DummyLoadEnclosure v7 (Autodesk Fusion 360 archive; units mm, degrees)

design "DummyLoadEnclosure" references "2.8 TFT Module"
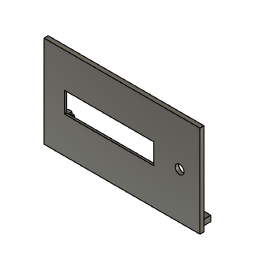
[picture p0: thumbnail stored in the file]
sketch "Sketch1" plane through (0, 0, 0) normal (0, 0, 1) x axis (1, 0, 0)
  line L1 (-60, -50) -> (60, -50)
  line L2 (-60, 50) -> (-60, -50)
  line L3 (60, 50) -> (-60, 50)
  line L4 (60, -50) -> (60, 50)
  line L5 (-60, 50) -> (60, -50)
  line L6 (60, 50) -> (-60, -50)
  point P6 (0, 0)
  point P1 (0, 0)
  point P4 (-60, 50)
  point P5 (60, 50)
  point P3 (-60, -50)
  horizontal L1
  perpendicular L1 L2
  parallel L1 L3
  parallel L2 L4
  coincident L5 P6
  coincident L6 P6
  coincident P1 P6
  dimension "d1" distance P4 P5 = 120
  dimension "d2" distance P3 P4 = 100
extrude "Extrude1" new body sketch "Sketch1" profile of L1 L2 L3 L4 along normal blind 70
shell "Shell1" innerThickness 3
split "Split1"
split "Split2"
split "Split3"
split "Split4"
combine "Combine1"
sketch "Sketch2" plane through (0, -47, 0) normal (0, -1, 0) x axis (1, 0, 0)
  line L1 (57, 70) -> (57, 67)
  line L2 (-57, 70) -> (57, 70)
  line L3 (-57, 67) -> (-57, 70)
  line L4 (57, 67) -> (-57, 67)
  line L5 (57, 70) -> (-57, 70)
  line L6 (57, 67) -> (57, 70)
  line L7 (-57, 67) -> (57, 67)
  line L8 (-57, 70) -> (-57, 67)
  point P2 (57, 67)
  point P8 (57, 67)
  point P4 (-57, 70)
  point P6 (-57, 70)
  horizontal L5
  vertical L6
  horizontal L7
  vertical L8
  coincident P2 P8
  coincident P4 P6
extrude "Extrude2" add sketch "Sketch2" along normal blind 10
sketch "Sketch3" plane through (0, -50, 0) normal (0, -1, 0) x axis (1, 0, 0)
  line L1 (57, 0) -> (57, 67)
  line L2 (60, 0) -> (57, 0)
  line L3 (60, 70) -> (60, 0)
  line L4 (57, 70) -> (60, 70)
  line L5 (57, 67) -> (57, 70)
  line L6 (60, 70) -> (57, 70)
  line L7 (60, 0) -> (60, 70)
  line L8 (57, 0) -> (60, 0)
  line L9 (57, 70) -> (57, 0)
  line L10 (-57, 70) -> (-60, 70)
  line L11 (-57, 0) -> (-57, 70)
  line L12 (-60, 0) -> (-57, 0)
  line L13 (-60, 70) -> (-60, 0)
  point P4 (60, 0)
  point P9 (60, 0)
  point P6 (57, 70)
  point P7 (57, 70)
  horizontal L6
  vertical L7
  horizontal L8
  vertical L9
  coincident P4 P9
  coincident P6 P7
  horizontal L10
  vertical L11
  horizontal L12
  vertical L13
extrude "Extrude3" add sketch "Sketch3" profile of L1 L2 L3 L4 L5 L6 L7 L8 L9 along normal blind 7
extrude "Extrude4" add sketch "Sketch3" profile of L10 L11 L12 L13 along normal blind 7
work_plane "WorkPlane1" AlongDistance -3
draft "Draft1" Angle1 -6 Angle2 0
combine "Combine2"
work_plane "WorkPlane5" AlongDistance -8.5 (= "( -17 / 2 ) * 1 mm")
work_plane "WorkPlane6" AlongDistance -8.5 (= "( -17 / 2 ) * 1 mm")
work_plane "WorkPlane7" AlongDistance -5
component_insert "Component Insert"
work_plane "WorkPlane8" AlongDistance -33
work_plane "WorkPlane9" AlongDistance -8
work_plane "WorkPlane10" AlongDistance -8
work_plane "WorkPlane11" AlongDistance -10.5
sketch "Sketch7" plane through (0, -47, 0) normal (0, 1, 0) x axis (-1, 0, 0)
  line L1 (-57, 67) -> (57, 67)
  line L2 (-57, 0) -> (-57, 67)
  line L3 (57, 0) -> (-57, 0)
  line L4 (57, 67) -> (57, 0)
  line L5 (46.5, 59) -> (-24, 59)
  line L6 (46.5, 8) -> (46.5, 59)
  line L7 (-24, 8) -> (46.5, 8)
  line L8 (-24, 59) -> (-24, 8)
  horizontal L5
  vertical L6
  horizontal L7
  vertical L8
position "Position4"
sketch "Sketch10" plane through (0, -47, 0) normal (0, 1, 0) x axis (-1, 0, 0)
  line L1 (-57, 67) -> (57, 67)
  line L2 (-57, 0) -> (-57, 67)
  line L3 (57, 0) -> (-57, 0)
  line L4 (57, 67) -> (57, 0)
  circle C1 centre (-27.3414, 55.3636) radius 1.6129
  circle C2 centre (48.757, 55.3636) radius 1.6129
  circle C3 centre (48.757, 11.447) radius 1.6129
  circle C4 centre (-27.3414, 11.447) radius 1.6129
  circle C5 centre (-27.3414, 55.3636) radius 3
  circle C6 centre (48.757, 55.3636) radius 3
  circle C7 centre (48.757, 11.447) radius 3
  circle C8 centre (-27.3414, 11.447) radius 3
  concentric C1 C5
  concentric C2 C6
  concentric C3 C7
  concentric C4 C8
  dimension "d34" diameter C5 = 6
  dimension "d35" diameter C6 = 6
  dimension "d36" diameter C7 = 6
  dimension "d37" diameter C8 = 6
sketch "Sketch11" plane through (0, -47, 0) normal (0, 1, 0) x axis (-1, 0, 0)
sketch "Sketch12" plane through (57, 0, 0) normal (-1, 0, 0) x axis (0, -1, 0)
  line L1 (-47, 67) -> (57, 67)
  line L2 (-47, 70) -> (-47, 67)
  line L3 (-50, 70) -> (-47, 70)
  line L4 (-50, 0) -> (-50, 70)
  line L5 (49.958, 0) -> (-50, 0)
  line L6 (57, 67) -> (49.958, 0)
  line L7 (45.9991, 67) -> (46.9991, 67)
  line L8 (45.9991, 3) -> (45.9991, 67)
  line L9 (46.9991, 3) -> (45.9991, 3)
  line L10 (46.9991, 67) -> (46.9991, 3)
  point P8 (46.9991, 67)
  point P9 (45.9991, 67)
  horizontal L7
  vertical L8
  horizontal L9
  vertical L10
  coincident L1 P8
  dimension "d58" distance P8 P9 = 1
extrude "Extrude14" add sketch "Sketch12" profile of L1 L7 L8 L9 L10 along normal blind 1
sketch "Sketch13" plane through (0, 0, 67) normal (0, 0, -1) x axis (1, 0, 0)
  line L1 (56, 45.9991) -> (57, 45.9991)
  line L2 (56, 46.9991) -> (56, 45.9991)
  line L3 (57, 46.9991) -> (56, 46.9991)
  line L4 (57, 57) -> (57, 46.9991)
  line L5 (-57, 57) -> (57, 57)
  line L6 (-57, -47) -> (-57, 57)
  line L7 (57, -47) -> (-57, -47)
  line L8 (57, 45.9991) -> (57, -47)
  line L9 (-57, 46.9991) -> (57, 46.9991)
  line L10 (-57, 45.9991) -> (-57, 46.9991)
  line L11 (57, 45.9991) -> (-57, 45.9991)
  line L12 (57, 46.9991) -> (57, 45.9991)
  point P5 (57, 46.9991)
  point P10 (57, 46.9991)
  point P11 (-57, 46.9991)
  point P13 (57, 45.9991)
  horizontal L9
  vertical L10
  horizontal L11
  vertical L12
  coincident P5 P10
  dimension "d61" distance P10 P11 = 114
  dimension "d62" distance P10 P13 = 1
extrude "Extrude15" add sketch "Sketch13" profile of L2 L6 L9 L10 L11 along normal blind 1
work_plane "WorkPlane12"
mirror "Mirror1" mirrorStitchTolerance 0.1
extrude "Extrude16" add of existing geometry blind 3
combine "Combine8"
sketch "Sketch14" plane through (0, 0, 67) normal (0, 0, -1) x axis (1, 0, 0)
  line L1 (57, 46.9991) -> (-57, 46.9991)
  line L2 (57, 57) -> (57, 46.9991)
  line L3 (-57, 57) -> (57, 57)
  line L4 (-57, 46.9991) -> (-57, 57)
work_plane "WorkPlane13" AlongDistance 3
sketch "Sketch15" plane through (0, 0, 67) normal (0, 0, -1) x axis (1, 0, 0)
  line L1 (-57, 50) -> (57, 50)
  line L2 (-57, 51) -> (-57, 50)
  line L3 (57, 51) -> (-57, 51)
  line L4 (57, 50) -> (57, 51)
  point P2 (57, 50)
  point P3 (-57, 50)
  point P5 (57, 51)
  horizontal L1
  vertical L2
  horizontal L3
  vertical L4
  dimension "d70" distance P2 P3 = 114
  dimension "d71" distance P2 P5 = 1
extrude "Extrude17" add sketch "Sketch15" along normal blind 1
offset_faces "OffsetFaces1" distance -0.2
position "Position5"
work_plane "WorkPlane16" AlongDistance -15
work_plane "WorkPlane15"
hole "Hole5" HoleDepth 5 HoleDiameter 6.5 TipAngle 180
chamfer "Chamfer2" distance 0.5
work_plane "WorkPlane17" AlongDistance -3
sketch "Sketch16" plane through (0, -47, 0) normal (0, 1, 0) x axis (-1, 0, 0)
  line L1 (-57, 67) -> (57, 67)
  line L2 (-57, 0) -> (-57, 67)
  line L3 (57, 0) -> (-57, 0)
  line L4 (57, 67) -> (57, 0)
  line L5 (-57, 3) -> (56.9, 3)
  line L6 (-57, 7) -> (-57, 3)
  line L7 (56.9, 7) -> (-57, 7)
  line L8 (56.9, 3) -> (56.9, 7)
  circle C1 centre (-41.9997, 33.4999) radius 3.75
  point P7 (56.9, 3)
  point P10 (56.9, 7)
  horizontal L5
  vertical L6
  horizontal L7
  vertical L8
  dimension "d96" distance P7 P10 = 4
extrude "Extrude19" add sketch "Sketch16" profile of L2 L5 L6 L7 L8 along normal blind 6
combine "Combine9"
extrude "Extrude20" cut of existing geometry blind -1
extrude "Extrude21" cut of existing geometry blind -0.9
work_plane "WorkPlane18"
sketch "Sketch17" plane through (0, 0, 7) normal (0, 0, 1) x axis (-1, 0, 0)
  line L1 (56, 46.9991) -> (56, 41)
  line L2 (56.9, 46.9991) -> (56, 46.9991)
  line L3 (56.9, 47) -> (56.9, 46.9991)
  line L4 (-57, 47) -> (56.9, 47)
  line L5 (-57, 46.9991) -> (-57, 47)
  line L6 (-56, 46.9991) -> (-57, 46.9991)
  line L7 (-56, 41) -> (-56, 46.9991)
  line L8 (56, 41) -> (-56, 41)
  dimension "d105" R-Pattern1-uDistance = 100
  dimension "d106" R-Pattern1-vDistance = 0
hole "Hole6" HoleDepth 50 HoleDiameter 1.6 TipAngle 180
sketch "Sketch18" plane through (0, 0, 0) normal (0, 0, -1) x axis (1, 0, 0)
  line L1 (57, -47) -> (-57, -47)
  line L2 (57, 47) -> (57, -47)
  line L3 (-57, 47) -> (57, 47)
  line L4 (-57, -47) -> (-57, 47)
  circle C1 centre (-25.0001, 44) radius 0.8
  circle C2 centre (24.9999, 44) radius 0.8
  circle C3 centre (49.9999, 44) radius 0.8
  circle C4 centre (-0.0001, 44) radius 0.8
  circle C5 centre (-50.0001, 44) radius 0.8
  circle C6 centre (49.9999, 44) radius 1.1
  circle C7 centre (24.9999, 44) radius 1.1
  circle C8 centre (-0.0001, 44) radius 1.1
  circle C9 centre (-25.0001, 44) radius 1.1
  circle C10 centre (-50.0001, 44) radius 1.1
  concentric C3 C6
  concentric C2 C7
  concentric C4 C8
  concentric C1 C9
  concentric C5 C10
  dimension "d110" diameter C6 = 2.2
  dimension "d111" diameter C7 = 2.2
  dimension "d112" diameter C8 = 2.2
  dimension "d113" diameter C9 = 2.2
  dimension "d114" diameter C10 = 2.2
hole "Hole7" HoleDepth 3 HoleDiameter 2.2 TipAngle 180
sketch "Sketch19" plane through (0, 0, 0) normal (0, 0, -1) x axis (1, 0, 0)
  line L1 (57, -47) -> (-57, -47)
  line L2 (57, 47) -> (57, -47)
  line L3 (-57, 47) -> (57, 47)
  line L4 (-57, -47) -> (-57, 47)
  line L5 (-52, 47) -> (-57, 47)
  line L6 (-52, 42) -> (-52, 47)
  line L7 (-57, 42) -> (-52, 42)
  line L8 (-57, 47) -> (-57, 42)
  line L9 (52, 47) -> (57, 47)
  line L10 (52, 42) -> (52, 47)
  line L11 (57, 42) -> (52, 42)
  line L12 (57, 47) -> (57, 42)
  line L13 (-52, -47) -> (-57, -47)
  line L14 (-52, -42) -> (-52, -47)
  line L15 (-57, -42) -> (-52, -42)
  line L16 (-57, -47) -> (-57, -42)
  line L17 (52, -47) -> (57, -47)
  line L18 (52, -42) -> (52, -47)
  line L19 (57, -42) -> (52, -42)
  line L20 (57, -47) -> (57, -42)
  circle C1 centre (24.9999, 44) radius 1.1
  circle C2 centre (-25.0001, 44) radius 1.1
  circle C3 centre (-50.0001, 44) radius 1.1
  circle C4 centre (-0.0001, 44) radius 1.1
  circle C5 centre (49.9999, 44) radius 1.1
  point P10 (-57, 47)
  point P11 (-57, 47)
  point P9 (57, 47)
  point P15 (57, 47)
  point P7 (-57, -47)
  point P19 (-57, -47)
  point P8 (57, -47)
  point P23 (57, -47)
  point P12 (-52, 47)
  point P14 (-57, 42)
  point P16 (52, 47)
  point P18 (57, 42)
  point P20 (-52, -47)
  point P22 (-57, -42)
  point P24 (52, -47)
  point P26 (57, -42)
  horizontal L5
  vertical L6
  horizontal L7
  vertical L8
  coincident P10 P11
  horizontal L9
  vertical L10
  horizontal L11
  vertical L12
  coincident P9 P15
  horizontal L13
  vertical L14
  horizontal L15
  vertical L16
  coincident P7 P19
  horizontal L17
  vertical L18
  horizontal L19
  vertical L20
  coincident P8 P23
  dimension "d118" distance P11 P12 = 5
  dimension "d119" distance P11 P14 = 5
  dimension "d120" distance P15 P16 = 5
  dimension "d121" distance P15 P18 = 5
  dimension "d122" distance P19 P20 = 5
  dimension "d123" distance P19 P22 = 5
  dimension "d124" distance P23 P24 = 5
  dimension "d125" distance P23 P26 = 5
extrude "Extrude22" add sketch "Sketch19" profile of L1 L2 L3 L4 L5 L6 L7 L8 L9 L10 L11 L12 L13 L14 L15 L16 L17 L18 L19 L20 along normal blind 2
chamfer "Chamfer7" distance 0.5
chamfer "Chamfer8" distance 0.5
chamfer "Chamfer9" distance 0.5
chamfer "Chamfer10" distance 0.5
chamfer "Chamfer11" distance 0.5
work_plane "WorkPlane19"
sketch "Sketch20" plane through (0, 47, 0) normal (0, -1, 0) x axis (1, 0, 0)
  line L1 (-57, 67) -> (57, 67)
  line L2 (-57, 0) -> (-57, 67)
  line L3 (57, 0) -> (-57, 0)
  line L4 (57, 67) -> (57, 0)
  line L5 (56, 2.9999) -> (-56, 2.9999)
  line L6 (56, 6.9999) -> (56, 2.9999)
  line L7 (-56, 6.9999) -> (56, 6.9999)
  line L8 (-56, 2.9999) -> (-56, 6.9999)
  line L9 (57, 3) -> (-57, 3)
  point P6 (-56, 2.9999)
  point P9 (-56, 6.9999)
  horizontal L5
  vertical L6
  horizontal L7
  vertical L8
  dimension "d133" distance P6 P9 = 4
  dimension "d134" distance L2 L8 = 1
  dimension "d136" distance L4 L6 = 1
extrude "Extrude23" add sketch "Sketch20" profile of L6 L7 L8 L9 along normal blind 6
sketch "Sketch21" plane through (0, 0, 6.9999) normal (0, 0, 1) x axis (-1, 0, 0)
  line L1 (56, -47) -> (-56, -47)
  line L2 (56, -41) -> (56, -47)
  line L3 (-56, -41) -> (56, -41)
  line L4 (-56, -47) -> (-56, -41)
  point P6 (50, -44)
  dimension "d139" distance L1 P6 = 3
  dimension "d140" distance L2 P6 = 6
  dimension "d143" R-Pattern1-uDistance = -100
  dimension "d144" R-Pattern1-vDistance = 0
hole "Hole8" HoleDepth 10 HoleDiameter 1.6 TipAngle 180
sketch "Sketch22" plane through (0, 0, 0) normal (0, 0, -1) x axis (1, 0, 0)
  line L1 (-52, -47) -> (-52, -42)
  line L2 (52, -47) -> (-52, -47)
  line L3 (52, -42) -> (52, -47)
  line L4 (57, -42) -> (52, -42)
  line L5 (57, 42) -> (57, -42)
  line L6 (52, 42) -> (57, 42)
  line L7 (52, 47) -> (52, 42)
  line L8 (-52, 47) -> (52, 47)
  line L9 (-52, 42) -> (-52, 47)
  line L10 (-57, 42) -> (-52, 42)
  line L11 (-57, -42) -> (-57, 42)
  line L12 (-52, -42) -> (-57, -42)
  circle C1 centre (50, -44) radius 0.8
  circle C2 centre (-25, -44) radius 0.8
  circle C3 centre (-50, -44) radius 0.8
  circle C4 centre (0, -44) radius 0.8
  circle C5 centre (25, -44) radius 0.8
  circle C6 centre (24.9999, 44) radius 1.6
  circle C7 centre (-25.0001, 44) radius 1.6
  circle C8 centre (-50.0001, 44) radius 1.6
  circle C9 centre (-0.0001, 44) radius 1.6
  circle C10 centre (49.9999, 44) radius 1.6
  circle C11 centre (-50, -44) radius 1.1
  circle C12 centre (-25, -44) radius 1.1
  circle C13 centre (0, -44) radius 1.1
  circle C14 centre (25, -44) radius 1.1
  circle C15 centre (50, -44) radius 1.1
  concentric C3 C11
  concentric C2 C12
  concentric C4 C13
  concentric C5 C14
  concentric C1 C15
  dimension "d148" diameter C11 = 2.2
  dimension "d149" diameter C12 = 2.2
  dimension "d150" diameter C13 = 2.2
  dimension "d151" diameter C14 = 2.2
  dimension "d152" diameter C15 = 2.2
hole "Hole9" HoleDepth 4 HoleDiameter 2.2 TipAngle 180
chamfer "Chamfer12" distance 0.5
chamfer "Chamfer13" distance 0.5
chamfer "Chamfer14" distance 0.5
hole "Hole10" HoleDepth 4 HoleDiameter 8 TipAngle 180 RefDim1 10 RefDim2 25
hole "Hole11" HoleDepth 4 HoleDiameter 6.5 TipAngle 180 RefDim1 70 RefDim2 25
extrude "Extrude24" add of existing geometry blind 1
sketch "Sketch23" plane through (0, 0, 67) normal (0, 0, -1) x axis (1, 0, 0)
  line L1 (-57, 45.9991) -> (57, 45.9991)
  line L2 (-57, -51) -> (-57, 45.9991)
  line L3 (57, -51) -> (-57, -51)
  line L4 (57, 45.9991) -> (57, -51)
  line L5 (-57, -51) -> (57, -51)
  line L6 (-57, -50) -> (-57, -51)
  line L7 (57, -50) -> (-57, -50)
  line L8 (57, -51) -> (57, -50)
  line L9 (-57, -47) -> (57, -47)
  line L10 (-57, -46) -> (-57, -47)
  line L11 (57, -46) -> (-57, -46)
  line L12 (57, -47) -> (57, -46)
  point P5 (57, -51)
  point P6 (57, -51)
  point P10 (57, -47)
  point P9 (57, -50)
  point P11 (-57, -47)
  point P13 (57, -46)
  horizontal L5
  vertical L6
  horizontal L7
  vertical L8
  coincident P5 P6
  horizontal L9
  vertical L10
  horizontal L11
  vertical L12
  coincident L4 P10
  dimension "d171" distance P6 P9 = 1
  dimension "d172" distance P10 P11 = 114
  dimension "d173" distance P10 P13 = 1
  dimension "d174" distance L7 L9 = 3
extrude "Extrude25" add sketch "Sketch23" profile of L2 L3 L4 L5 L6 L7 L8 L9 L10 L11 L12 along normal blind 2
offset_faces "OffsetFaces2" distance -0.2
offset_faces "OffsetFaces3" distance -0.2
offset_faces "OffsetFaces4" distance -0.2
offset_faces "OffsetFaces5" distance -0.2
offset_faces "OffsetFaces6" distance -0.2
chamfer "Chamfer15" distance 0.5
chamfer "Chamfer16" distance 0.5
extrude "Extrude26" cut of existing geometry blind -0.2
extrude "Extrude27" add of existing geometry blind 1
offset_faces "OffsetFaces7" distance -0.2
offset_faces "OffsetFaces8" distance -0.2
offset_faces "OffsetFaces9" distance -0.2
offset_faces "OffsetFaces10" distance -0.1
sketch "Sketch24" plane through (0, 0, 3) normal (0, 0, 1) x axis (-1, 0, 0)
  line L1 (57, -47) -> (-57, -47)
  line L2 (57, 47) -> (57, -47)
  line L3 (-57, 47) -> (57, 47)
  line L4 (-57, -47) -> (-57, 47)
  line L5 (51, 9) -> (57, 9)
  line L6 (51, -9) -> (51, 9)
  line L7 (57, -9) -> (51, -9)
  line L8 (57, 9) -> (57, -9)
  line L9 (68.4, 0) -> (-68.4, 0)
  circle C1 centre (25, -44) radius 1.1
  circle C2 centre (-25, -44) radius 1.1
  circle C3 centre (-50, -44) radius 1.1
  circle C4 centre (0, -44) radius 1.1
  circle C5 centre (50, -44) radius 1.1
  circle C6 centre (-24.9999, 44) radius 1.1
  circle C7 centre (25.0001, 44) radius 1.1
  circle C8 centre (50.0001, 44) radius 1.1
  circle C9 centre (0.0001, 44) radius 1.1
  circle C10 centre (-49.9999, 44) radius 1.1
  point P16 (57, 9)
  horizontal L5
  vertical L6
  horizontal L7
  vertical L8
  coincident L2 P16
  dimension "d192" distance L7 L9 = 9
  dimension "d193" distance L5 L9 = 9
  dimension "d194" distance L2 L6 = 6
extrude "Extrude28" add sketch "Sketch24" profile of L2 L5 L6 L7 L8 L9 along normal blind 6
work_plane "WorkPlane20"
mirror "Mirror2" mirrorStitchTolerance 0.1
hole "Hole12" HoleDepth 6 HoleDiameter 2.5 TipAngle 180 RefDim1 3 RefDim2 9
mirror "Mirror3" mirrorStitchTolerance 0.1
thread "Thread5" ThreadOffset 0 ThreadLength 10
thread "Thread6" ThreadOffset 0 ThreadLength 10
chamfer "Chamfer17" distance 0.5
chamfer "Chamfer18" distance 0.5
sketch "Sketch25" plane through (57, 0, 0) normal (-1, 0, 0) x axis (0, -1, 0)
  line L1 (-46, 65) -> (-46, 67)
  line L2 (-46.8, 65) -> (-46, 65)
  line L3 (-46.8, 67.2) -> (-46.8, 65)
  line L4 (-50, 67.2) -> (-46.8, 67.2)
  line L5 (-50, 65) -> (-50, 67.2)
  line L6 (-51, 65) -> (-50, 65)
  line L7 (-51, 0) -> (-51, 65)
  line L8 (49.958, 0) -> (-51, 0)
  line L9 (57, 67) -> (49.958, 0)
  line L10 (51, 67) -> (57, 67)
  line L11 (51, 66) -> (51, 67)
  line L12 (50.2, 66) -> (51, 66)
  line L13 (50.2, 67) -> (50.2, 66)
  line L14 (46.9991, 67) -> (50.2, 67)
  line L15 (46.9991, 3) -> (46.9991, 67)
  line L16 (45.9991, 3) -> (46.9991, 3)
  line L17 (45.9991, 67) -> (45.9991, 3)
  line L18 (-46, 67) -> (45.9991, 67)
  circle C1 centre (0, 6) radius 1.75
  dimension "d208" diameter C1 = 3.5
extrude "Extrude29" cut sketch "Sketch25" profile of C1 against normal blind 3
sketch "Sketch26" plane through (-57, 0, 0) normal (1, 0, 0) x axis (0, 1, 0)
  line L1 (46, 67) -> (46, 65)
  line L2 (-45.9991, 67) -> (46, 67)
  line L3 (-45.9991, 3) -> (-45.9991, 67)
  line L4 (-46.9991, 3) -> (-45.9991, 3)
  line L5 (-46.9991, 67) -> (-46.9991, 3)
  line L6 (-50.2, 67) -> (-46.9991, 67)
  line L7 (-50.2, 66) -> (-50.2, 67)
  line L8 (-51, 66) -> (-50.2, 66)
  line L9 (-51, 67) -> (-51, 66)
  line L10 (-57, 67) -> (-51, 67)
  line L11 (-49.958, 0) -> (-57, 67)
  line L12 (51, 0) -> (-49.958, 0)
  line L13 (51, 65) -> (51, 0)
  line L14 (50, 65) -> (51, 65)
  line L15 (50, 67.2) -> (50, 65)
  line L16 (46.8, 67.2) -> (50, 67.2)
  line L17 (46.8, 65) -> (46.8, 67.2)
  line L18 (46, 65) -> (46.8, 65)
  circle C1 centre (0, 6) radius 1.75
  dimension "d211" diameter C1 = 3.5
extrude "Extrude30" cut sketch "Sketch26" profile of C1 against normal blind 3
chamfer "Chamfer19" distance 0.5
chamfer "Chamfer20" distance 0.5
chamfer "Chamfer21" distance 0.5
sketch "Sketch27" plane through (0, 0, 9) normal (0, 0, 1) x axis (-1, 0, 0)
  line L1 (57, 9) -> (57, -9)
  line L2 (51, 9) -> (57, 9)
  line L3 (51, -9) -> (51, 9)
  line L4 (57, -9) -> (51, -9)
  circle C1 centre (54, 6) radius 0.8
  circle C2 centre (54, -6) radius 0.8
  point P6 (54, 6)
  point P8 (54, 6)
  point P7 (54, -6)
  point P9 (54, -6)
  coincident P6 P8
  coincident P7 P9
  dimension "d217" distance L3 P6 = 3
  dimension "d218" distance L2 P6 = 3
  dimension "d219" distance L4 P7 = 3
  dimension "d220" distance L3 P7 = 3
  dimension "d221" diameter C1 = 1.6
  dimension "d222" diameter C2 = 1.6
extrude "Extrude31" cut sketch "Sketch27" profile of C1 against normal blind 10
extrude "Extrude32" cut sketch "Sketch27" profile of C2 against normal blind 10
sketch "Sketch28" plane through (0, 0, 0) normal (0, 0, -1) x axis (1, 0, 0)
  line L1 (57, 42) -> (57, -42)
  line L2 (52, 42) -> (57, 42)
  line L3 (52, 47) -> (52, 42)
  line L4 (-52, 47) -> (52, 47)
  line L5 (-52, 42) -> (-52, 47)
  line L6 (-57, 42) -> (-52, 42)
  line L7 (-57, -42) -> (-57, 42)
  line L8 (-52, -42) -> (-57, -42)
  line L9 (-52, -47) -> (-52, -42)
  line L10 (52, -47) -> (-52, -47)
  line L11 (52, -42) -> (52, -47)
  line L12 (57, -42) -> (52, -42)
  circle C1 centre (-54, -6) radius 0.8
  circle C2 centre (-54, 6) radius 0.8
  circle C3 centre (25, -44) radius 1.6
  circle C4 centre (-25, -44) radius 1.6
  circle C5 centre (49.9999, 44) radius 1.6
  circle C6 centre (-0.0001, 44) radius 1.6
  circle C7 centre (-50.0001, 44) radius 1.6
  circle C8 centre (-25.0001, 44) radius 1.6
  circle C9 centre (24.9999, 44) radius 1.6
  circle C10 centre (-50, -44) radius 1.6
  circle C11 centre (0, -44) radius 1.6
  circle C12 centre (50, -44) radius 1.6
  circle C13 centre (-54, 6) radius 1.1
  circle C14 centre (-54, -6) radius 1.1
  concentric C2 C13
  concentric C1 C14
  dimension "d227" diameter C13 = 2.2
  dimension "d228" diameter C14 = 2.2
extrude "Extrude33" cut sketch "Sketch28" profile of C1 C2 C13 C14 against normal blind 3
split "Split5" bodies "Base (1)", "DummyLoadBaseTopMount"
remove_body "RemoveBody1"
mirror "Mirror4" mirrorStitchTolerance 0.1 bodies "DummyLoadBase"
extrude "Extrude34" cut of existing geometry blind -10
extrude "Extrude35" cut of existing geometry blind -10
remove_body "RemoveBody2"
remove_body "RemoveBody3"
sketch "Sketch29" plane through (0, 47, 0) normal (0, -1, 0) x axis (1, 0, 0)
  line L1 (55.8, 6.9999) -> (-55.8, 6.9999)
  line L2 (55.8, 3) -> (55.8, 6.9999)
  line L3 (-55.8, 3) -> (55.8, 3)
  line L4 (-55.8, 6.9999) -> (-55.8, 3)
  line L5 (-56.8, 67) -> (56.8, 67)
  line L6 (-56.8, 0) -> (-56.8, 67)
  line L7 (56.8, 0) -> (-56.8, 0)
  line L8 (56.8, 67) -> (56.8, 0)
  line L9 (-44.7, 44) -> (-21.7, 44)
  line L10 (-44.7, 36) -> (-44.7, 44)
  line L11 (-21.7, 36) -> (-44.7, 36)
  line L12 (-21.7, 44) -> (-21.7, 36)
  line L13 (-44.7, 36) -> (-21.7, 44)
  line L14 (-21.7, 36) -> (-44.7, 44)
  line L15 (-40.6, 45.8) -> (-25.8, 45.8)
  line L16 (-40.6, 47.8) -> (-40.6, 45.8)
  line L17 (-25.8, 47.8) -> (-40.6, 47.8)
  line L18 (-25.8, 45.8) -> (-25.8, 47.8)
  circle C1 centre (-13, 25) radius 3.75
  circle C2 centre (47, 25) radius 4.5
  point P16 (-33.2, 40)
  point P14 (-44.7, 36)
  point P15 (-21.7, 36)
  point P13 (-44.7, 44)
  point P17 (-25.8, 45.8)
  point P18 (-40.6, 45.8)
  point P20 (-25.8, 47.8)
  horizontal L9
  perpendicular L9 L10
  parallel L9 L11
  parallel L10 L12
  coincident L13 P16
  coincident L14 P16
  horizontal L15
  vertical L16
  horizontal L17
  vertical L18
  dimension "d237" distance P14 P15 = 23
  dimension "d238" distance P13 P14 = 8
  dimension "d239" distance L8 P16 = 90
  dimension "d240" distance P17 P18 = 14.8
  dimension "d241" distance P17 P20 = 2
  dimension "d242" distance L12 L18 = 4.1
  dimension "d243" distance L9 L15 = 1.8
sketch "Sketch30" plane through (0, 47, 0) normal (0, -1, 0) x axis (1, 0, 0)
  line L1 (55.8, 6.9999) -> (-55.8, 6.9999)
  line L2 (55.8, 3) -> (55.8, 6.9999)
  line L3 (-55.8, 3) -> (55.8, 3)
  line L4 (-55.8, 6.9999) -> (-55.8, 3)
  line L5 (-56.8, 67) -> (56.8, 67)
  line L6 (-56.8, 0) -> (-56.8, 67)
  line L7 (56.8, 0) -> (-56.8, 0)
  line L8 (56.8, 67) -> (56.8, 0)
  curve K1
  curve K2
  curve K3
  curve K4
  circle C1 centre (-13, 25) radius 3.75
  circle C2 centre (47, 25) radius 4.5
  dimension "d259" distance L6 K4 = 10
  dimension "d260" distance L5 K3 = 5
  dimension "d258" Text1-Height = 10
extrude "Extrude38" add sketch "Sketch30" along normal blind 0.5
sketch "Sketch31" plane through (0, 47, 0) normal (0, -1, 0) x axis (1, 0, 0)
  curve K1 (-45.463, 60.7688) -> (-46.8, 56.8704)
  curve K2 (-42.0115, 62.1774) -> (-45.463, 60.7688)
  curve K3 (-39.5149, 61.5157) -> (-42.0115, 62.1774)
  curve K4 (-37.8198, 59.6705) -> (-39.5149, 61.5157)
  curve K5 (-37.2366, 56.9864) -> (-37.8198, 59.6705)
  curve K6 (-37.8505, 54.2647) -> (-37.2366, 56.9864)
  curve K7 (-39.5899, 52.4468) -> (-37.8505, 54.2647)
  curve K8 (-42.0183, 51.8295) -> (-39.5899, 52.4468)
  curve K9 (-44.5422, 52.5116) -> (-42.0183, 51.8295)
  curve K10 (-46.227, 54.3738) -> (-44.5422, 52.5116)
  curve K11 (-46.8, 56.8704) -> (-46.227, 54.3738)
  line L1 (-7.0046, 57.0614) -> (-3.4439, 52)
  line L2 (-8.6417, 55.4652) -> (-7.0046, 57.0614)
  line L3 (-8.6417, 52) -> (-8.6417, 55.4652)
  line L4 (-9.9651, 52) -> (-8.6417, 52)
  line L5 (-0.6472, 62) -> (-0.6472, 52)
  line L6 (3.1045, 62) -> (-0.6472, 62)
  line L7 (34.1004, 52) -> (34.1004, 53.1801)
  line L8 (27.4906, 52) -> (34.1004, 52)
  line L9 (-13.287, 59.0873) -> (-12.0183, 59.1828)
  line L10 (-36.3293, 53.2278) -> (-36.3293, 52)
  line L11 (-31.2065, 59.633) -> (-36.3293, 53.2278)
  curve K12 (-30.1697, 60.8199) -> (-31.2065, 59.633)
  line L12 (-35.7495, 60.8199) -> (-30.1697, 60.8199)
  line L13 (-35.7495, 62) -> (-35.7495, 60.8199)
  line L14 (-28.5872, 62) -> (-35.7495, 62)
  line L15 (-28.5872, 60.8199) -> (-28.5872, 62)
  line L16 (-34.2011, 53.8827) -> (-28.5872, 60.8199)
  line L17 (-34.8082, 53.1801) -> (-34.2011, 53.8827)
  line L18 (-28.4235, 53.1801) -> (-34.8082, 53.1801)
  line L19 (-28.4235, 52) -> (-28.4235, 53.1801)
  line L20 (-36.3293, 52) -> (-28.4235, 52)
  line L21 (55.8, 6.9999) -> (-55.8, 6.9999)
  line L22 (55.8, 3) -> (55.8, 6.9999)
  line L23 (-55.8, 3) -> (55.8, 3)
  line L24 (-55.8, 6.9999) -> (-55.8, 3)
  line L25 (-56.8, 67) -> (56.8, 67)
  line L26 (-56.8, 0) -> (-56.8, 67)
  line L27 (56.8, 0) -> (-56.8, 0)
  line L28 (56.8, 67) -> (56.8, 0)
  curve K13 (4.7791, 52.1671) -> (5.8739, 52.6617)
  curve K14 (3.1659, 52) -> (4.7791, 52.1671)
  curve K15 (13.657, 53.1801) -> (14.1754, 53.8452)
  curve K16 (20.243, 59.7865) -> (19.878, 56.9318)
  curve K17 (21.3276, 61.4543) -> (20.243, 59.7865)
  curve K18 (23.1386, 62.0409) -> (21.3276, 61.4543)
  curve K19 (24.5506, 61.7169) -> (23.1386, 62.0409)
  curve K20 (25.5533, 60.7824) -> (24.5506, 61.7169)
  curve K21 (26.1741, 59.2954) -> (25.5533, 60.7824)
  curve K22 (26.3992, 56.9318) -> (26.1741, 59.2954)
  curve K23 (24.9565, 52.4195) -> (26.0377, 54.0907)
  curve K24 (23.1386, 51.8295) -> (24.9565, 52.4195)
  curve K25 (20.8671, 52.8663) -> (23.1386, 51.8295)
  curve K26 (19.878, 56.9318) -> (20.8671, 52.8663)
  curve K27 (12.095, 52.8527) -> (11.9517, 52)
  curve K28 (12.9033, 54.1828) -> (12.095, 52.8527)
  curve K29 (14.5097, 55.6971) -> (12.9033, 54.1828)
  curve K30 (16.713, 57.8151) -> (14.5097, 55.6971)
  curve K31 (17.286, 59.292) -> (16.713, 57.8151)
  curve K32 (16.7641, 60.5232) -> (17.286, 59.292)
  curve K33 (15.4033, 61.0246) -> (16.7641, 60.5232)
  curve K34 (13.9844, 60.4925) -> (15.4033, 61.0246)
  line L29 (-9.9651, 62) -> (-9.9651, 52)
  line L30 (-8.6417, 62) -> (-9.9651, 62)
  line L31 (-8.6417, 57.0409) -> (-8.6417, 62)
  line L32 (-3.6758, 62) -> (-8.6417, 57.0409)
  line L33 (-1.8819, 62) -> (-3.6758, 62)
  line L34 (-6.0769, 57.9482) -> (-1.8819, 62)
  line L35 (-1.6977, 52) -> (-6.0769, 57.9482)
  line L36 (-3.4439, 52) -> (-1.6977, 52)
  line L37 (-27.4139, 61.8704) -> (-27.4139, 60.6903)
  curve K35 (-22.8334, 58.2142) -> (-20.9405, 60.9154)
  curve K36 (-24.2829, 54.749) -> (-22.8334, 58.2142)
  curve K37 (-24.7536, 52) -> (-24.2829, 54.749)
  curve K38 (-25.5517, 54.8513) -> (-26.0156, 52)
  curve K39 (-24.2795, 58.0744) -> (-25.5517, 54.8513)
  curve K40 (-22.5162, 60.6903) -> (-24.2795, 58.0744)
  curve K41 (-18.0176, 54.0907) -> (-18.4303, 55.322)
  curve K42 (-17.0115, 53.3131) -> (-18.0176, 54.0907)
  curve K43 (-15.4767, 53.0164) -> (-17.0115, 53.3131)
  curve K44 (-14.1397, 53.2415) -> (-15.4767, 53.0164)
  curve K45 (-13.2768, 53.8588) -> (-14.1397, 53.2415)
  curve K46 (-12.9937, 54.7149) -> (-13.2768, 53.8588)
  curve K47 (-13.2666, 55.5368) -> (-12.9937, 54.7149)
  curve K48 (-14.167, 56.1269) -> (-13.2666, 55.5368)
  curve K49 (-15.9473, 56.6146) -> (-14.167, 56.1269)
  curve K50 (-17.8778, 57.2387) -> (-15.9473, 56.6146)
  line L38 (-19, 19) -> (-7, 19)
  line L39 (-19, 31) -> (-19, 19)
  line L40 (-7, 31) -> (-19, 31)
  line L41 (-7, 19) -> (-7, 31)
  line L42 (-19, 31) -> (-7, 19)
  line L43 (-7, 31) -> (-19, 19)
  curve K51 (26.0377, 54.0907) -> (26.3992, 56.9318)
  curve K52 (27.6338, 52.8527) -> (27.4906, 52)
  curve K53 (28.4422, 54.1828) -> (27.6338, 52.8527)
  curve K54 (30.0486, 55.6971) -> (28.4422, 54.1828)
  curve K55 (32.2518, 57.8151) -> (30.0486, 55.6971)
  curve K56 (32.8248, 59.292) -> (32.2518, 57.8151)
  curve K57 (32.303, 60.5232) -> (32.8248, 59.292)
  curve K58 (30.9422, 61.0246) -> (32.303, 60.5232)
  curve K59 (29.5233, 60.4925) -> (30.9422, 61.0246)
  curve K60 (28.9844, 59.0191) -> (29.5233, 60.4925)
  line L44 (27.7225, 59.1487) -> (28.9844, 59.0191)
  curve K61 (28.698, 61.3008) -> (27.7225, 59.1487)
  curve K62 (30.9694, 62.0409) -> (28.698, 61.3008)
  curve K63 (33.2477, 61.2428) -> (30.9694, 62.0409)
  curve K64 (34.0868, 59.2647) -> (33.2477, 61.2428)
  curve K65 (33.8412, 58.0846) -> (34.0868, 59.2647)
  curve K66 (33.0261, 56.8636) -> (33.8412, 58.0846)
  curve K67 (31.1332, 55.1037) -> (33.0261, 56.8636)
  curve K68 (29.7143, 53.8452) -> (31.1332, 55.1037)
  curve K69 (29.1959, 53.1801) -> (29.7143, 53.8452)
  line L45 (34.1004, 53.1801) -> (29.1959, 53.1801)
  line L46 (18.5615, 52) -> (18.5615, 53.1801)
  line L47 (11.9517, 52) -> (18.5615, 52)
  curve K70 (13.4456, 59.0191) -> (13.9844, 60.4925)
  line L48 (12.1836, 59.1487) -> (13.4456, 59.0191)
  curve K71 (13.1591, 61.3008) -> (12.1836, 59.1487)
  curve K72 (15.4306, 62.0409) -> (13.1591, 61.3008)
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  point P107 (-13, 25)
  point P37 (-13, 25)
  point P105 (-19, 31)
  point P106 (-7, 31)
  point P104 (-19, 19)
  horizontal L38
  perpendicular L38 L39
  parallel L38 L40
  parallel L39 L41
  coincident L42 P107
  coincident L43 P107
  coincident P37 P107
  dimension "d265" distance P105 P106 = 12
  dimension "d266" distance P104 P105 = 12
sketch "Sketch32" plane through (60, 0, 0) normal (1, 0, 0) x axis (0, 1, 0)
  line L1 (51, 0) -> (-49.958, 0)
  line L2 (51, 70) -> (51, 0)
  line L3 (-57.3153, 70) -> (51, 70)
  line L4 (-49.958, 0) -> (-57.3153, 70)
  line L5 (21, 30) -> (20, 30)
  line L6 (21, 10) -> (21, 30)
  line L7 (20, 10) -> (21, 10)
  line L8 (20, 30) -> (20, 10)
  line L9 (23, 10) -> (23, 30)
  line L10 (23, 30) -> (22, 30)
  line L11 (22, 30) -> (22, 10)
  line L12 (22, 10) -> (23, 10)
  line L13 (25, 10) -> (25, 30)
  line L14 (25, 30) -> (24, 30)
  line L15 (24, 30) -> (24, 10)
  line L16 (24, 10) -> (25, 10)
  line L17 (27, 10) -> (27, 30)
  line L18 (27, 30) -> (26, 30)
  line L19 (26, 30) -> (26, 10)
  line L20 (26, 10) -> (27, 10)
  line L21 (29, 10) -> (29, 30)
  line L22 (29, 30) -> (28, 30)
  line L23 (28, 30) -> (28, 10)
  line L24 (28, 10) -> (29, 10)
  line L25 (31, 10) -> (31, 30)
  line L26 (31, 30) -> (30, 30)
  line L27 (30, 30) -> (30, 10)
  line L28 (30, 10) -> (31, 10)
  line L29 (33, 10) -> (33, 30)
  line L30 (33, 30) -> (32, 30)
  line L31 (32, 30) -> (32, 10)
  line L32 (32, 10) -> (33, 10)
  line L33 (35, 10) -> (35, 30)
  line L34 (35, 30) -> (34, 30)
  line L35 (34, 30) -> (34, 10)
  line L36 (34, 10) -> (35, 10)
  circle C1 centre (0, 6) radius 2.25
  point P7 (20, 30)
  point P8 (21, 30)
  point P10 (20, 10)
  horizontal L5
  vertical L6
  horizontal L7
  vertical L8
  dimension "d272" distance P7 P8 = 1
  dimension "d273" distance P7 P10 = 20
  dimension "d274" distance L1 L7 = 10
  dimension "d277" R-Pattern1-uDistance = 14
  dimension "d278" R-Pattern1-vDistance = 0
extrude "Extrude40" cut sketch "Sketch32" profile of L5 L6 L7 L8 L9 L10 L11 L12 L13 L14 L15 L16 L17 L18 L19 L20 L21 L22 L23 L24 L25 L26 L27 L28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 against normal blind 3
work_plane "WorkPlane21"
mirror "Mirror5" mirrorStitchTolerance 0.1
extrude "Extrude41" add of existing geometry blind 4
extrude "Extrude42" add of existing geometry blind 2
fillet "Fillet5" radius 18
fillet "Fillet6" radius 18
fillet "Fillet7" radius 30
fillet "Fillet8" radius 10
fillet "Fillet9" radius 10
fillet "Fillet10" radius 10
chamfer "Chamfer24" distance 0.5
chamfer "Chamfer25" distance 0.5
work_plane "WorkPlane1" AlongDistance -10
work_plane "WorkPlane2" AlongDistance -85
work_plane "WorkPlane3" AlongDistance 16
work_plane "WorkPlane4" AlongDistance -15
sketch "Sketch1" plane through (0, -45.1968, 0) normal (0, 1, 0) x axis (-1, 0, 0)
  line L1 (56.6579, 10.1381) -> (-57.0421, 10.1381)
  line L2 (56.6579, 70.1381) -> (56.6579, 10.1381)
  line L3 (-57.0421, 70.1381) -> (56.6579, 70.1381)
  line L4 (-57.0421, 10.1381) -> (-57.0421, 70.1381)
  circle C1 centre (-42.2419, 36.638) radius 3.75
  circle C2 centre (-28.3341, 52.6417) radius 3.5
  circle C3 centre (46.66, 52.64) radius 3.5
  circle C4 centre (46.6587, 21.6614) radius 3.5
  circle C5 centre (-28.3478, 21.6318) radius 3.5
  dimension "d305" diameter C2 = 7
  dimension "d306" diameter C3 = 7
  dimension "d307" diameter C4 = 7
  dimension "d308" diameter C5 = 7
extrude "Extrude43" add sketch "Sketch1" profile of C2 C3 C4 C5 along normal blind 6
hole "Hole16" HoleDepth 8 HoleDiameter 1.4 TipAngle 180
hole "Hole17" HoleDepth 8 HoleDiameter 1.4 TipAngle 180
hole "Hole18" HoleDepth 8 HoleDiameter 1.4 TipAngle 180
hole "Hole19" HoleDepth 8 HoleDiameter 1.4 TipAngle 180
work_plane "WorkPlane5" AlongDistance -8
work_plane "WorkPlane6" AlongDistance 8
work_plane "WorkPlane7" AlongDistance -5
work_plane "WorkPlane8" AlongDistance 5
sketch "Sketch2" plane through (0, -45.1968, 0) normal (0, 1, 0) x axis (-1, 0, 0)
  line L1 (56.6579, 10.1381) -> (-57.0421, 10.1381)
  line L2 (56.6579, 70.1381) -> (56.6579, 10.1381)
  line L3 (-57.0421, 70.1381) -> (56.6579, 70.1381)
  line L4 (-57.0421, 10.1381) -> (-57.0421, 70.1381)
  line L5 (41.6585, 44.6531) -> (-23.3425, 44.6531)
  line L6 (41.6585, 29.6374) -> (41.6585, 44.6531)
  line L7 (-23.3425, 29.6374) -> (41.6585, 29.6374)
  line L8 (-23.3425, 44.6531) -> (-23.3425, 29.6374)
  circle C1 centre (-28.3478, 21.6318) radius 3.5
  circle C2 centre (-28.3341, 52.6417) radius 3.5
  circle C3 centre (46.6587, 21.6614) radius 3.5
  circle C4 centre (46.66, 52.64) radius 3.5
  circle C5 centre (-42.2419, 36.638) radius 3.75
  horizontal L5
  vertical L6
  horizontal L7
  vertical L8
extrude "Extrude44" cut sketch "Sketch2" profile of L5 L6 L7 L8 against normal blind 10
fillet "Fillet11" radius 2
fillet "Fillet12" radius 2
fillet "Fillet14" radius 2
chamfer "Chamfer26" distance 0.5
delete_face "DeleteFace1"
delete_face "DeleteFace2"
fillet "Fillet15" radius 2
chamfer "Chamfer27" distance 0.5
fillet "Fillet16" radius 2
chamfer "Chamfer28" distance 0.5
work_plane "WorkPlane9" AlongDistance -3
work_plane "WorkPlane10" AlongDistance 2
work_plane "WorkPlane11" AlongDistance 1.5
work_plane "WorkPlane12" AlongDistance -1.5
sketch "Sketch3" plane through (0, -45.1968, 0) normal (0, 1, 0) x axis (-1, 0, 0)
  line L1 (56.6579, 10.1381) -> (-57.0421, 10.1381)
  line L2 (56.6579, 70.1381) -> (56.6579, 10.1381)
  line L3 (-57.0421, 70.1381) -> (56.6579, 70.1381)
  line L4 (-57.0421, 10.1381) -> (-57.0421, 70.1381)
  line L5 (41.6585, 29.6374) -> (41.6585, 44.6531)
  line L6 (-23.3425, 29.6374) -> (41.6585, 29.6374)
  line L7 (-23.3425, 44.6531) -> (-23.3425, 29.6374)
  line L8 (41.6585, 44.6531) -> (-23.3425, 44.6531)
  line L9 (45.2, 49.6388) -> (-26.8425, 49.6388)
  line L10 (45.2, 23.6) -> (45.2, 49.6388)
  line L11 (-26.8425, 23.6) -> (45.2, 23.6)
  line L12 (-26.8425, 49.6388) -> (-26.8425, 23.6)
  circle C1 centre (-28.3478, 21.6318) radius 5.5
  circle C2 centre (46.66, 52.64) radius 5.5
  circle C3 centre (-42.2419, 36.638) radius 3.75
  circle C4 centre (-28.3341, 52.6417) radius 5.5
  circle C5 centre (46.6587, 21.6614) radius 5.5
  horizontal L9
  vertical L10
  horizontal L11
  vertical L12
extrude "Extrude45" cut sketch "Sketch3" profile of C1 L5 L6 L7 L8 C5 L9 L10 L11 L12 against normal blind 1.5
work_plane "WorkPlane22" AlongDistance -1.5
sketch "Sketch34" plane through (0, -48.5, 0) normal (0, 1, 0) x axis (1, 0, 0)
  line L1 (-45.4677, -46.9872) -> (26.3509, -46.9872)
  line L2 (-45.4677, -20.5011) -> (-45.4677, -46.9872)
  line L3 (26.3509, -20.5011) -> (-45.4677, -20.5011)
  line L4 (26.3509, -46.9872) -> (26.3509, -20.5011)
  horizontal L1
  vertical L2
  horizontal L3
  vertical L4
extrude "Extrude46" cut sketch "Sketch34" along normal blind 15
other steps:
create_component "CreateComponent1"
named bodies: "DummyLoadFront", "DummyLoadBack", "DummyLoadTop", "Base", "Base (1)", "DummyLoadBaseTopMount", "DummyLoadBase"

design "2.8 TFT Module"
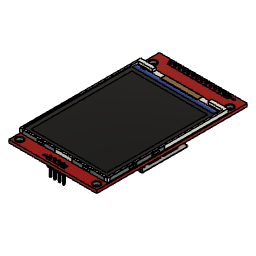
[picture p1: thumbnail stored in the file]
